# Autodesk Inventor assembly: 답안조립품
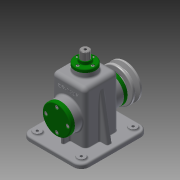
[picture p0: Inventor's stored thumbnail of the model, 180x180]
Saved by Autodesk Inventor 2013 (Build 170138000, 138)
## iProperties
Created: 2016-01
Part Number: 답안조립품
Document SubType Name: Assembly
Designer: Administrator
Author: Administrator
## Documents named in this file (19)
- C:\Users\Administrator\Desktop\460127V1018\답안조립품.iam
- C:\Users\Administrator\Desktop\460127V1018\1본체.ipt
- C:\Users\Administrator\Desktop\460127V1018\V-벨트풀리.ipt
- C:\Users\Administrator\Desktop\460127V1018\고정핀.ipt
- C:\Users\Administrator\Desktop\460127V1018\뒤커버.ipt
- C:\Users\Administrator\Desktop\460127V1018\링크.ipt
- C:\Users\Administrator\Desktop\460127V1018\멈춤링 6 x 5.ipt
- C:\Users\Administrator\Desktop\460127V1018\멈춤링 15 x 1.ipt
- C:\Users\Administrator\Desktop\460127V1018\베어링 15 x 35 x 11.ipt
- C:\Users\Administrator\Desktop\460127V1018\볼트 M3 x 8.ipt
- C:\Users\Administrator\Desktop\460127V1018\볼트 M4 x 10.ipt
- C:\Users\Administrator\Desktop\460127V1018\볼트 M6 x 12.ipt
- C:\Users\Administrator\Desktop\460127V1018\상부부시.ipt
- C:\Users\Administrator\Desktop\460127V1018\슬라이드바.ipt
- C:\Users\Administrator\Desktop\460127V1018\앞커버.ipt
- C:\Users\Administrator\Desktop\460127V1018\오일실 15 25 7.ipt
- C:\Users\Administrator\Desktop\460127V1018\와셔.ipt
- C:\Users\Administrator\Desktop\460127V1018\키 5 x 5 x 14.ipt
- C:\Users\Administrator\Desktop\460127V1018\편심축.ipt
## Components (16 placed, 6 different names)
1. 1본체:1
2. V-벨트풀리:1 — 각도:2
3. 고정핀:1
4. ISO 4018 M6 x 12:1
5. ISO 4762 M3 x 8:1
6. ISO 4762 M3 x 8:2
7. ISO 4762 M3 x 8:3
8. ISO 4762 M3 x 8:4
9. ISO 4762 M4 x 10:1
10. ISO 4762 M4 x 10:3
11. ISO 4762 M4 x 10:4
12. ISO 4762 M4 x 10:5
13. ISO 4762 M4 x 10:2
14. ISO 4762 M4 x 10:6
15. ISO 4762 M4 x 10:7
16. ISO 4762 M4 x 10:8
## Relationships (1: Angle 1)
- 각도:2 [Angle]: V-벨트풀리:1
